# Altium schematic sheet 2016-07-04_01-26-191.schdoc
size 217 x 116 mm; SheetNumber: 1; SheetTotal: 1
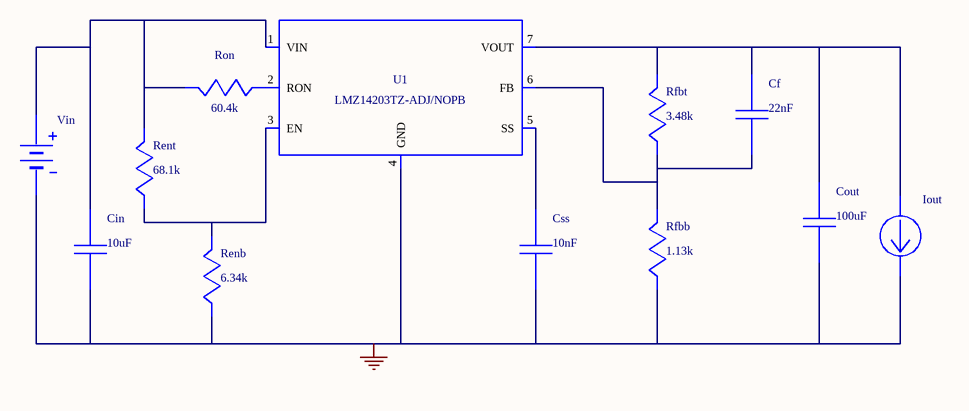
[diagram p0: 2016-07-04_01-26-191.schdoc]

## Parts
Cf  value 22nF  (hidden comment: CC0805KRX7R9BB223)
Cin  value 10uF  (hidden comment: GRM32ER7YA106KA12L)
Cout  value 100uF  (hidden comment: GRM31CR60J107ME39L)
Css  value 10nF  (hidden comment: GRM216R71H103KA01D)
Iout  WB_CURRENT_LOAD  (value not drawn)
Renb  value 6.34k  (hidden comment: ERJ-6ENF6341V)
Rent  value 68.1k  (hidden comment: ERJ-6ENF6812V)
Rfbb  value 1.13k  (hidden comment: ERJ-6ENF1131V)
Rfbt  value 3.48k  (hidden comment: ERJ-6ENF3481V)
Ron  value 60.4k  (hidden comment: ERJ-6ENF6042V)
U1  LMZ14203TZ-ADJ/NOPB
Vin  WB_BATTERY  (value not drawn)

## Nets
0: Cin.2 Cout.2 Css.2 Iout.2(-) Renb.2 Rfbb.2 U1.4(GND) U1.8(EP) Vin.2(-)
NetCf_1: Cf.1 Cout.1 Iout.1(+) Rfbt.1 U1.7(VOUT)
NetCf_2: Cf.2 Rfbb.1 Rfbt.2 U1.6(FB)
NetCin_1: Cin.1 Rent.1 Ron.1 U1.1(VIN) Vin.1(+)
NetCss_1: Css.1 U1.5(SS)
NetRenb_1: Renb.1 Rent.2 U1.3(EN)
NetRon_2: Ron.2 U1.2(RON)

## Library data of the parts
Cf = CC0805KRX7R9BB223: CC0805KRX7R9BB22; Manufacturer Name: Yageo America
Cin = GRM32ER7YA106KA12L: GRM32ER7YA106KA1; Manufacturer Name: MuRata
Cout = GRM31CR60J107ME39L: GRM31CR60J107ME3; Manufacturer Name: MuRata
Css = GRM216R71H103KA01D: GRM216R71H103KA0; Manufacturer Name: MuRata
Renb = ERJ-6ENF6341V: Manufacturer Name: Panasonic
Rent = ERJ-6ENF6812V: Manufacturer Name: Panasonic
Rfbb = ERJ-6ENF1131V: Manufacturer Name: Panasonic
Rfbt = ERJ-6ENF3481V: Manufacturer Name: Panasonic
Ron = ERJ-6ENF6042V: Manufacturer Name: Panasonic
U1 = LMZ14203TZ-ADJ/NOPB: LMZ14203TZ-ADJ/N; Manufacturer Name: Texas Instruments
